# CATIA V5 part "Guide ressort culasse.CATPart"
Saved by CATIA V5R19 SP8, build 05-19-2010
Part number: Guide ressort culasse
Bounding box of the stored display mesh (mm): x -3.999 to 3.999, y 0 to 75.64, z -3.996 to 3.996
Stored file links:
  C:\Users\Arthur\Desktop\Catia parts\GLOCK\Ensemble culasse\Guide ressort culasse.CATPart
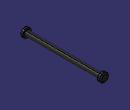
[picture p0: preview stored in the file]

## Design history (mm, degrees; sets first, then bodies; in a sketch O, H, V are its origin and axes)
Set1
  Sketch1 on yz-plane, origin (0, 0, 0), H (0, 1, 0), V (0, 0, 1)
    axis line L1 (-50, 0) -> (170, 0)
    line L2 (2, 2.5) -> (72.64, 2.5)
    point P4 (72.64, 2.5)
    line L3 (2, 2.5) -> (2, 4)
    line L4 (2, 4) -> (0, 4)
    line L5 (0, 4) -> (0, 0)
    point P7 (0, 0)
    line L6 (72.64, 2.5) -> (72.64, 4)
    point P8 (72.64, 4)
    line L7 (72.64, 4) -> (74.5793, 4)
    point P9 (75.64, 4)
    line L8 (75.64, 2.9393) -> (75.64, 0)
    point P10 (75.64, 0)
    line L9 (74.5793, 4) -> (75.64, 2.9393)
    distance L2 L1 = 2.5
    length L4 = 2
    distance P4 L5 = 72.64
    distance L4 L1 = 4
    distance P8 P9 = 3
    angle L7 L9 = 45
    length L9 = 1.5
    distance L7 L1 = 4
    horizontal: L1 H, L2 H, L4 H, L7 H
    coincidence: L1 H, L5 V, P7 L1, P10 L1, L7 P9, L8 P9
    vertical: L3 V, L5 V, L6 V, L8 V
Body1 (main body)
  Shaft1: profile Sketch1, axis Sketch1.L1, angle 360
